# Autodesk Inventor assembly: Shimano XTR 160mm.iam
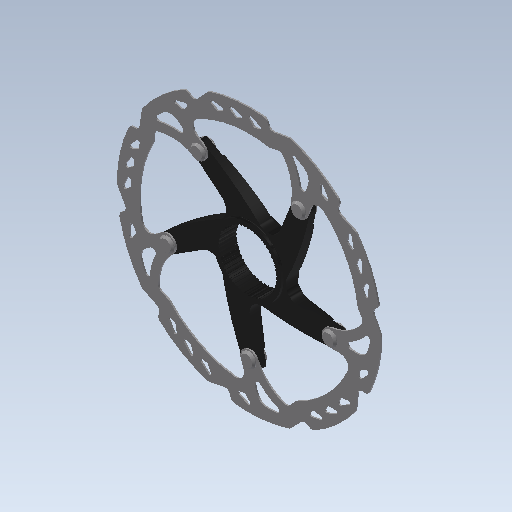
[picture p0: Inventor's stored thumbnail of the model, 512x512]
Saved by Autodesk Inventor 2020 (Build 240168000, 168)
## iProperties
Created: 2015-11
Part Number: Shimano XTR 160mm.iam
Material: Ogólny
Document SubType Name: Assembly
Designer: Tomasz
Sending System: SolidWorks 2017
Last Author: Tomasz
Last Saved: 2017-09-17
Author: Tomasz
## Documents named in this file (7)
- C:\Users\bruno\Documents\1-Cours-2020-21\1STI2D-2020-21\IT\6. Antivol\Inventor-Antivol\INVENTOR 2018_Steel Hardtail B+\Shimano XTR 160mm.iam.iam
- C:\Users\bruno\Documents\1-Cours-2020-21\1STI2D-2020-21\IT\6. Antivol\Inventor-Antivol\INVENTOR 2018_Steel Hardtail B+\Kopia disk rotor.ipt^Shimano XTR 160mm.iam.ipt
- C:\Users\bruno\Documents\1-Cours-2020-21\1STI2D-2020-21\IT\6. Antivol\Inventor-Antivol\INVENTOR 2018_Steel Hardtail B+\Kopia rotor spider.ipt^Shimano XTR 160mm.iam.ipt
- C:\Users\bruno\Documents\1-Cours-2020-21\1STI2D-2020-21\IT\6. Antivol\Inventor-Antivol\INVENTOR 2018_Steel Hardtail B+\Kopia nit.ipt^Shimano XTR 160mm.iam.ipt
- Kopia disk rotor.ipt^Shimano XTR 160mm.iam
- Kopia rotor spider.ipt^Shimano XTR 160mm.iam
- Kopia nit.ipt^Shimano XTR 160mm.iam
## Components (7 placed, 3 different names)
1. Kopia disk rotor.ipt^Shimano XTR 160mm.iam:1
2. Kopia rotor spider.ipt^Shimano XTR 160mm.iam:1
3. Kopia nit.ipt^Shimano XTR 160mm.iam:1
4. Kopia nit.ipt^Shimano XTR 160mm.iam:2
5. Kopia nit.ipt^Shimano XTR 160mm.iam:3
6. Kopia nit.ipt^Shimano XTR 160mm.iam:4
7. Kopia nit.ipt^Shimano XTR 160mm.iam:5
